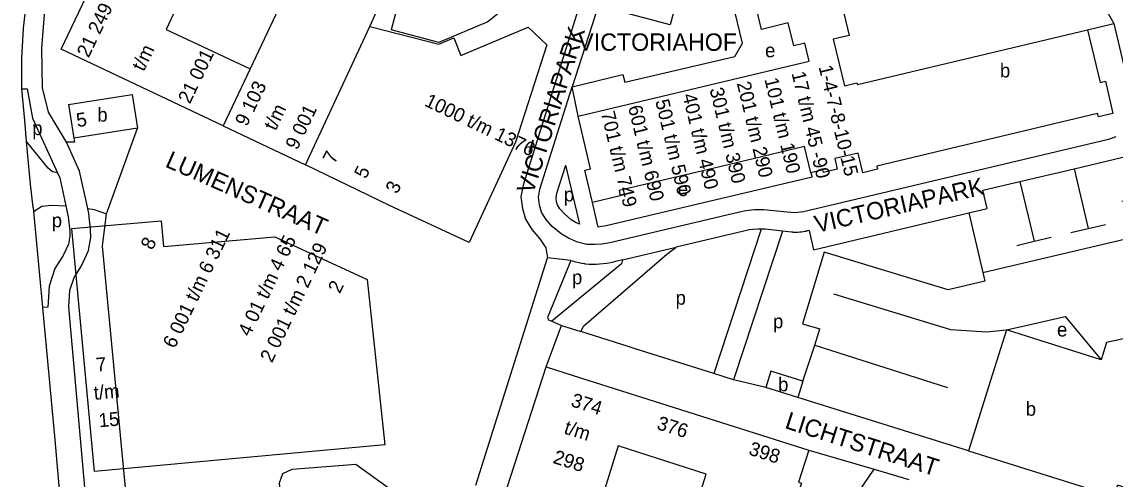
# Model space of a CAD drawing. Extents: x 160673 to 161924, y 382258 to 384145.
# Drawn here: x 160684.6 to 160999.1, y 383378.5 to 383510.1 of the extents above; entities that cross this region are included whole.
import ezdxf

# ---------------------------------------------------------------- set-up
doc = ezdxf.new("R2010")
doc.units = 0
for name, color, linetype in [('BLT_Basislijn', 7, 'Continuous'), ('BLT_Bebouwing', 7, 'Continuous'), ('BLT_Centroide', 7, 'Continuous'), ('BLT_Huisnummer', 7, 'Continuous'), ('BLT_Huisnummer_reeks', 7, 'Continuous'), ('BLT_Huisnummer_zonder_bebouwing', 7, 'Continuous'), ('BLT_Plantopo', 7, 'Continuous'), ('BLT_Straatnaam', 7, 'Continuous'), ('BLT_Straatnaam_verkleind', 7, 'Continuous'), ('BLT_Vlakafsluiter', 7, 'Continuous')]:
    doc.layers.add(name, color=color, linetype=linetype)

msp = doc.modelspace()

# ---------------------------------------------------------------- linework, layer by layer
at = {"layer": 'BLT_Basislijn'}
for p, q in [((160850.39, 383514.63), (160842.89, 383491.44)), ((160991.2, 383507.82), (160998.69, 383509.61)), ((160685.44, 383481.72), (160684.61, 383490.86)), ((160844.62, 383482.96), (160842.89, 383491.44)), ((160685.98, 383475.68), (160685.44, 383481.72)), ((160708.96, 383454.81), (160717.88, 383479.52)), ((160699.73, 383475.45), (160697.47, 383475.43)), ((160701.23, 383467.15), (160697.47, 383475.43)), ((160699.54, 383476.6), (160699.73, 383475.45)), ((160845.1, 383451.85), (160841.05, 383468.84)), ((160703.57, 383456.34), (160701.23, 383467.15)), ((160971.7, 383464.15), (160987.28, 383467.84)), ((160987.28, 383467.84), (160991.35, 383450.63)), ((160961.02, 383461.62), (160971.7, 383464.15)), ((160971.7, 383464.15), (160975.77, 383446.94)), ((160687.88, 383456.69), (160687.99, 383455.52)), ((160687.99, 383455.52), (160690.57, 383427.84)), ((160897.28, 383450.41), (160883.64, 383408.84)), ((160903.41, 383449.83), (160889.36, 383407.03)), ((160986.41, 383449.45), (160991.35, 383450.63)), ((160991.35, 383450.63), (160996.3, 383451.8)), ((160970.83, 383445.76), (160975.77, 383446.94)), ((160975.77, 383446.94), (160980.72, 383448.11)), ((160815.16, 383376.72), (160835.79, 383442.16)), ((160912.72, 383417.06), (160914.12, 383421.7)), ((160859.03, 383416.65), (160845.39, 383420.98)), ((160883.64, 383408.84), (160861.02, 383416.02)), ((160909.27, 383406.65), (160912.72, 383417.06)), ((160912.72, 383417.06), (160950.91, 383404.82)), ((160889.36, 383407.03), (160883.64, 383408.84)), ((160898.59, 383404.83), (160889.36, 383407.03)), ((160956.88, 383386.6), (160907.79, 383401.95))]:
    msp.add_line(p, q, dxfattribs=at)
for points in [[(160842.89, 383491.44), (160857.49, 383494.91), (160858.08, 383492.7), (160889.67, 383500.12), (160891.88, 383503.94), (160883.12, 383540.53), (160889.29, 383541.87)], [(160684.61, 383490.86), (160684.61, 383499.58), (160685.09, 383508.32), (160685.57, 383512.46), (160687.62, 383523.88), (160689.63, 383532.89)], [(160989.13, 383531.95), (160991.39, 383522.74), (160998.69, 383509.61)], [(160697.47, 383475.43), (160692.31, 383484.12), (160690.54, 383491.16), (160690.31, 383502.5), (160691.21, 383513.34), (160692.23, 383519.82), (160694.43, 383529.74)], [(160850.1, 383531.24), (160828.79, 383463.13), (160828.19, 383459.76), (160828.59, 383456.34), (160829.47, 383453.28), (160831.32, 383450.35), (160833.59, 383447.68), (160835.3, 383445.08), (160835.79, 383442.16)], [(160998.69, 383509.61), (161004.4, 383485.63)], [(160684.61, 383490.86), (160686.12, 383490.85), (160687.72, 383482.4), (160694.85, 383466.69)], [(160839.84, 383481.71), (160842.89, 383491.44)], [(160999.34, 383476.99), (160997.24, 383476.21), (160909.44, 383455.41), (160907.1, 383455.15), (160904.79, 383455.3), (160898.05, 383455.99), (160895.32, 383455.95), (160892.9, 383455.72), (160891.06, 383455.35), (160853.72, 383446.48), (160851.45, 383446.11), (160849.44, 383445.97), (160847.12, 383446.04), (160844.42, 383446.71), (160841.82, 383447.8), (160839.75, 383449.04), (160837.13, 383451.24), (160835.36, 383453.32), (160834.08, 383455.35), (160833.51, 383457.33), (160833.24, 383459.61), (160833.66, 383461.95), (160839.84, 383481.71)], [(160687.88, 383456.69), (160687.08, 383463.37), (160685.98, 383475.68)], [(160694.85, 383466.69), (160693.39, 383466.96), (160692.19, 383467.95), (160685.98, 383475.68)], [(160845.1, 383451.85), (160844.08, 383452.28), (160842.66, 383453.13), (160840.67, 383454.8), (160839.4, 383456.29), (160838.69, 383457.42), (160838.43, 383458.31), (160838.29, 383459.46), (160838.52, 383460.76), (160841.05, 383468.84)], [(160987.28, 383467.84), (161003.34, 383471.64), (161006.19, 383459.6), (161001.03, 383458.38)], [(160694.85, 383466.69), (160695.5, 383465.25), (160697.25, 383457.17)], [(160911.61, 383466.66), (160911.91, 383465.44), (160852.73, 383451.39), (160850.87, 383451.08), (160850.44, 383451.05)], [(160957, 383455.09), (160962.27, 383456.34), (160961.02, 383461.62)], [(160687.99, 383455.52), (160690.32, 383457.01), (160693.15, 383457.37), (160697.25, 383457.17)], [(160697.25, 383457.17), (160697.95, 383453.95), (160698.41, 383449.96), (160698.45, 383448.42), (160698.05, 383446.1), (160696.47, 383442.82), (160694.14, 383439.09), (160692.48, 383434), (160692.09, 383427.98), (160690.57, 383427.84)], [(160706.71, 383330.64), (160698.1, 383428.04), (160698.42, 383432.86), (160699.62, 383436.53), (160701.73, 383439.92), (160703.82, 383444.25), (160704.47, 383447.99), (160704.4, 383450.39), (160703.87, 383454.93), (160703.57, 383456.34)], [(160703.57, 383456.34), (160705.39, 383456.09), (160708.96, 383454.81)], [(160850.43, 383451.05), (160848.76, 383458.06)], [(160724.7, 383331.93), (160718.08, 383337.74), (160707.8, 383445.49), (160708.96, 383454.81)], [(160911.07, 383450.05), (160912.38, 383444.53), (160957, 383455.09)], [(160957, 383455.09), (160961.07, 383437.91)], [(160897.28, 383450.41), (160896.41, 383450.41), (160894.9, 383450.33), (160893.81, 383450.2), (160892.26, 383449.89), (160872.8, 383445.26)], [(160903.41, 383449.83), (160898.45, 383450.4), (160897.28, 383450.41)], [(160906.36, 383449.54), (160906, 383449.53), (160903.41, 383449.83)], [(160911.07, 383450.05), (160910.53, 383449.93), (160910.35, 383449.9)], [(160961.07, 383437.91), (161008.66, 383449.18), (161008.06, 383451.73)], [(160845.39, 383420.98), (160846.23, 383422.61), (160870.14, 383443.25), (160872.8, 383445.26)], [(160961.07, 383437.91), (160961.64, 383435.5), (160951.11, 383433.01), (160915.45, 383443.81), (160909.21, 383423.18), (160914.12, 383421.7)], [(160842.56, 383441.44), (160835.85, 383425), (160836.09, 383424.33), (160837.03, 383423.94)], [(160857.38, 383441.61), (160857.06, 383440.45), (160837.03, 383423.94)], [(160846.65, 383440.47), (160846.42, 383440.49), (160846.19, 383440.53)], [(160857.38, 383441.61), (160854.97, 383441.04), (160854.93, 383441.03)], [(160918.11, 383431.83), (160951.72, 383421.55), (160956.33, 383421.25), (160962.13, 383420.88), (160967.85, 383421.42)], [(160690.57, 383427.84), (160694.12, 383389.79), (160696.81, 383358.88), (160698.16, 383346.04)], [(160967.85, 383421.42), (160973.44, 383422.72), (160984.71, 383425.34), (160995.07, 383412.86)], [(160861.02, 383416.02), (160859.03, 383416.65)], [(160910.96, 383386.85), (160929.77, 383381.33)], [(160748.01, 383333.85), (160761.28, 383339.45), (160761.62, 383340.45), (160758.69, 383377.42), (160759.73, 383380.09), (160762.36, 383381.36), (160780.68, 383382.83), (160798.57, 383369.85)], [(160892.6, 383326.68), (160906.21, 383323.37), (160913.1, 383331.56), (160914.07, 383347.41), (160919.16, 383350.75), (160920.61, 383367.82), (160929.77, 383381.33)], [(160929.77, 383381.33), (160939.74, 383378.41)]]:
    msp.add_lwpolyline(points, dxfattribs=at)
for centre, radius, start, end in [((160905.95, 383476.59), 27.05, 270.8763, 279.3557), ((160850.17, 383464.12), 23.92, 251.4261, 260.4151), ((160848.97, 383468), 27.63, 265.1917, 282.4537)]:
    msp.add_arc(centre, radius, start, end, dxfattribs=at)
at = {"layer": 'BLT_Bebouwing'}
for p, q in [((160698, 383486.3), (160716.37, 383489.22)), ((160698, 383486.3), (160699.54, 383476.6)), ((160717.88, 383479.52), (160699.54, 383476.6)), ((160995.07, 383412.86), (160967.85, 383421.42)), ((160823.3, 383373.06), (160835.39, 383410.83)), ((160835.39, 383410.83), (160845.3, 383407.68)), ((160900.06, 383409.54), (160898.59, 383404.83)), ((160909.27, 383406.65), (160900.06, 383409.54)), ((160845.3, 383407.68), (160910.96, 383386.85)), ((160909.27, 383406.65), (160907.79, 383401.95)), ((160907.79, 383401.95), (160898.59, 383404.83)), ((160856.13, 383388.07), (160842.09, 383342.93)), ((160881.51, 383379.91), (160856.13, 383388.07)), ((160867.04, 383334.9), (160881.51, 383379.91))]:
    msp.add_line(p, q, dxfattribs=at)
for points in [[(160867.86, 383547.96), (160882.4, 383551.52), (160871.13, 383509.23), (160858.45, 383512.62)], [(160724.99, 383547.34), (160740.93, 383539.56), (160744.15, 383543.28), (160811.79, 383525.14), (160810.21, 383519.26), (160794.99, 383523.45), (160790.82, 383507.82)], [(160913.94, 383547.72), (160914.96, 383543.48), (160913.77, 383543.19), (160922.57, 383506.21), (160918.01, 383505.13), (160921.27, 383491.7), (160924.79, 383492.55), (160924.95, 383492.07), (160991.2, 383507.82)], [(160844.62, 383482.96), (160911.11, 383498.75), (160909.88, 383503.98), (160906.7, 383503.19), (160905.09, 383509.78), (160897.39, 383507.93), (160889.29, 383541.87)], [(160835.61, 383523.91), (160818.62, 383510.07), (160804.56, 383504.15), (160790.82, 383507.82)], [(160991.2, 383507.82), (160994.81, 383492.67), (160996.31, 383493.02), (160998.48, 383483.77), (160994.3, 383482.79), (160994, 383483.69), (160930.54, 383468.59), (160930.76, 383467.68), (160926.56, 383466.68), (160925.19, 383472.34), (160918.44, 383470.74), (160919.18, 383467.68), (160915.24, 383466.73), (160915.05, 383467.5), (160911.61, 383466.66)], [(160716.37, 383489.22), (160717.88, 383479.52)], [(160848.76, 383458.06), (160846.53, 383467.42), (160848.19, 383467.83), (160844.62, 383482.96)], [(160911.61, 383466.66), (160909.78, 383474.2), (160883.36, 383467.93), (160856.4, 383461.53), (160856.75, 383459.98), (160848.76, 383458.06)], [(161022.99, 383428.61), (161021.27, 383423.17), (160996.63, 383417.81), (160995.07, 383412.86)], [(160967.85, 383421.42), (160963.25, 383406.83)], [(160963.25, 383406.83), (160956.88, 383386.6)], [(160956.88, 383386.6), (160998.82, 383373.47), (160999.85, 383376.81), (161000, 383376.76), (161006.6, 383374.71), (161011.97, 383391.9), (161032.55, 383385.51)], [(160910.96, 383386.85), (160908.05, 383377.58), (160908.9, 383377.28), (160892.6, 383326.68)]]:
    msp.add_lwpolyline(points, dxfattribs=at)
at = {"layer": 'BLT_Plantopo'}
msp.add_line((160742.55, 383480.14), (160766.18, 383468.95), dxfattribs=at)
for points in [[(160695.94, 383502.2), (160714.21, 383540.7), (160718.7, 383550.41), (160740.93, 383539.56), (160726.08, 383507.92), (160750.26, 383496.57), (160742.55, 383480.14)], [(160784.69, 383508.72), (160804.59, 383503.68), (160808.91, 383505.51), (160810.91, 383500.42), (160830.27, 383508.56), (160835.63, 383503.52), (160826.59, 383475.43), (160813.3, 383446.63), (160790.38, 383457.24), (160766.18, 383468.95)], [(160698.97, 383450.61), (160724.69, 383452.84), (160725.33, 383445.44), (160757.39, 383448.22), (160783.96, 383435.9), (160789.05, 383388.35), (160705.53, 383380.67)]]:
    msp.add_lwpolyline(points, close=True, dxfattribs=at)
msp.add_lwpolyline([(160784.69, 383508.72), (160788.4, 383516.92), (160764.92, 383527.8), (160750.26, 383496.57)], dxfattribs=at)
at = {"layer": 'BLT_Vlakafsluiter'}
for p, q in [((160857.38, 383441.61), (160872.8, 383445.26)), ((160842.56, 383441.44), (160835.79, 383442.16)), ((160835.39, 383410.83), (160839.88, 383422.73)), ((160837.03, 383423.94), (160839.88, 383422.73)), ((160839.88, 383422.73), (160845.39, 383420.98))]:
    msp.add_line(p, q, dxfattribs=at)

# ---------------------------------------------------------------- texts
at = {"layer": 'BLT_Centroide'}
for s, p in [('e', (160898.4, 383499.9)), ('b', (160965.97, 383494.12)), ('b', (160706.31, 383481.38)), ('p', (160687.6, 383477.52)), ('e', (160873.31, 383459.95)), ('p', (160840.51, 383458.42)), ('p', (160693.21, 383450.98)), ('p', (160842.86, 383434.59)), ('p', (160872.67, 383428.69)), ('p', (160900.68, 383421.91)), ('e', (160982.38, 383419.54)), ('b', (160902.15, 383403.76)), ('b', (160973.39, 383396.72))]:
    msp.add_text(s, height=4, dxfattribs=at).set_placement(p)
at = {"layer": 'BLT_Huisnummer'}
msp.add_text('5', height=4, rotation=9.0722, dxfattribs=at).set_placement((160700.61, 383479.75))
at = {"layer": 'BLT_Huisnummer_reeks'}
for s, rotation, p in [('1-4-7-8-10-15', 283.5204, (160913.78, 383497.18)), ('101 t/m 190', 283.5204, (160898.2, 383493.57)), ('17 t/m 45 -90', 283.5204, (160905.99, 383495.36)), ('301 t/m 390', 283.5204, (160882.43, 383490.73)), ('201 t/m 290', 283.5204, (160890.25, 383492.43)), ('501 t/m 590', 283.5204, (160866.8, 383487.32)), ('401 t/m 490', 283.5204, (160874.62, 383489.02)), ('701 t/m 749', 283.5204, (160851.17, 383483.9)), ('601 t/m 690', 283.5204, (160858.98, 383485.62)), ('374', 342.3907, (160842.29, 383399.55)), ('376', 342.3904, (160866.99, 383392.95)), ('t/m', 342.3907, (160840.31, 383391.68)), ('398', 342.3907, (160893.45, 383385.6)), ('298', 342.3904, (160837.16, 383383.18))]:
    msp.add_text(s, height=4, rotation=rotation, dxfattribs=at).set_placement(p)
at = {"layer": 'BLT_Huisnummer_zonder_bebouwing'}
for s, rotation, p in [('21 249', 64.4065, (160703.81, 383499.54)), ('t/m', 64.4065, (160719.67, 383495.62)), ('21 001', 64.4065, (160732.93, 383486.26)), ('9 103', 64.4065, (160749.32, 383479.76)), ('1000 t/m 1376', 334.4065, (160800.17, 383486.06)), ('t/m', 64.4065, (160757.6, 383478.54)), ('9 001', 64.4065, (160763.82, 383473)), ('7', 64.4065, (160774.58, 383468.99)), ('5', 64.4065, (160783.6, 383464.69)), ('3', 64.4065, (160792.62, 383460.36)), ('6 001 t/m 6 311', 64.4065, (160728.58, 383415.86)), ('8', 64.4065, (160722.19, 383444.2)), ('4 01 t/m 4 65', 64.4065, (160750.17, 383419.28)), ('2 001 t/m 2 129', 64.4065, (160756.55, 383411.77)), ('2', 64.4065, (160776.08, 383431.7)), ('7', 5.0722, (160706.11, 383409.39)), ('t/m', 5.0722, (160705.46, 383401.3)), ('15', 5.0722, (160706.87, 383393.39))]:
    msp.add_text(s, height=4, rotation=rotation, dxfattribs=at).set_placement(p)
at = {"layer": 'BLT_Straatnaam'}
msp.add_text('VICTORIAHOF', height=5, dxfattribs=at).set_placement((160844.65, 383501.77))
for s, rotation, p in [('LUMENSTRAAT', 336.1928, (160725.55, 383468.51)), ('VICTORIAPARK', 13, (160913.28, 383449.32)), ('LICHTSTRAAT', 342.1928, (160903.83, 383393.23))]:
    msp.add_text(s, height=5, rotation=rotation, dxfattribs=at).set_placement(p)
at = {"layer": 'BLT_Straatnaam_verkleind'}
msp.add_text('VICTORIAPARK', height=5, rotation=72.4168, dxfattribs=at).set_placement((160831.65, 383460.29))

doc.saveas('drawing.dxf')
